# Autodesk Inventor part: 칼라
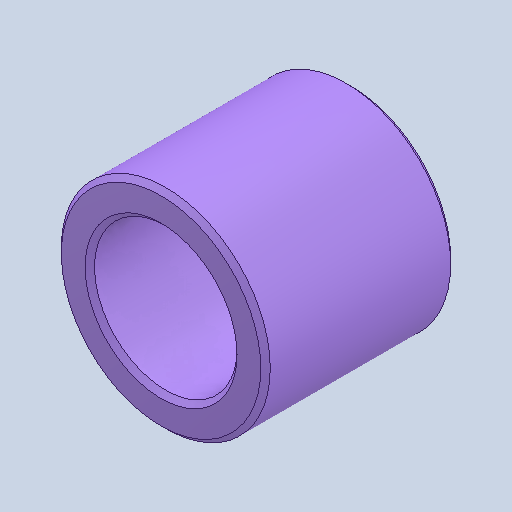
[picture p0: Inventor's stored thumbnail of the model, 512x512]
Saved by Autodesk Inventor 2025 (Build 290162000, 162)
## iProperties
Created: 2024-07
Part Number: 칼라
Material: 스테인리스강
Document SubType Name: Modeling
Designer: anfro
Density: 8.08 g/cm^3
Appearance: 기본값
Author: jhkim
Sending System: Autodesk Inventor 2025
Preprocessor: ST-DEVELOPER v20
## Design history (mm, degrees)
feature "솔리드1"
node "솔리드2"
